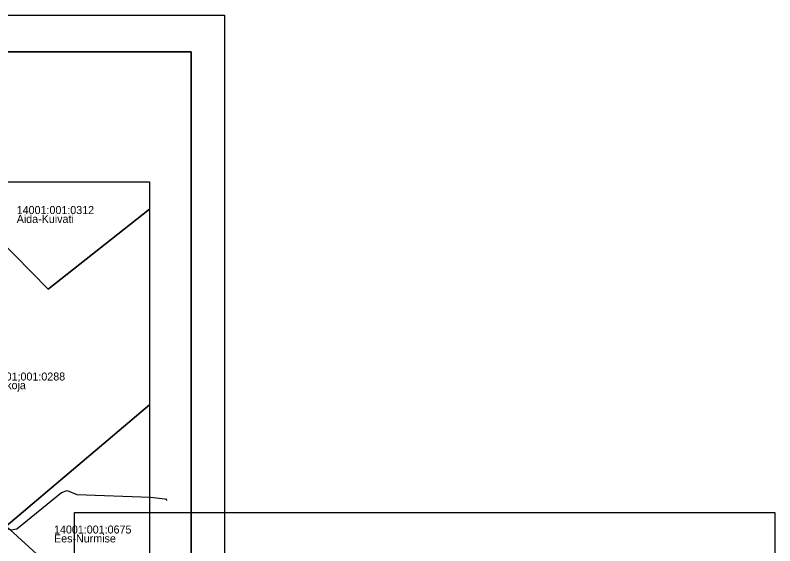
# Model space of a CAD drawing. Extents: x 567864 to 568657, y 6579839 to 6580994.
# Drawn here: x 568478.2 to 568649.1, y 6580409.7 to 6580529 of the extents above; entities that cross this region are included whole.
import ezdxf

# ---------------------------------------------------------------- set-up
doc = ezdxf.new("R2010")
doc.units = 0
for name, color, linetype in [('PIIR', 7, 'Continuous'), ('PR_SIDE', 7, 'Continuous'), ('VORMISTUS_3', 7, 'Continuous'), ('VORMISTUS_4', 7, 'Continuous')]:
    doc.layers.add(name, color=color, linetype=linetype)

msp = doc.modelspace()

# ---------------------------------------------------------------- linework, layer by layer
at = {"layer": 'PIIR'}
for points in [[(568391.3, 6580491.46), (568392.03, 6580490.79), (568429.88, 6580456.3), (568437.22, 6580449.61), (568476.19, 6580414.1), (568508.43, 6580384.73)], [(568508.43, 6580485.34), (568485.66, 6580467.38), (568470.64, 6580482.56), (568461.73, 6580491.46)], [(568508.43, 6580441.35), (568476.19, 6580414.1), (568437.22, 6580449.61), (568470.64, 6580482.56), (568485.66, 6580467.38), (568508.43, 6580485.34)], [(568508.43, 6580384.73), (568476.19, 6580414.1), (568508.43, 6580441.35)]]:
    msp.add_lwpolyline(points, dxfattribs=at)
at = {"layer": 'PR_SIDE'}
msp.add_lwpolyline([(568437.29, 6580453.58), (568437.5, 6580453.08), (568436.5, 6580449.92), (568436.73, 6580448.74), (568445.54, 6580441.11), (568454.95, 6580432.52), (568470.37, 6580418.43), (568474.47, 6580414.72), (568476.09, 6580413.59), (568477.35, 6580413.23), (568478.62, 6580413.47), (568488.63, 6580421.66), (568489.89, 6580422.06), (568492.08, 6580421.21), (568508.66, 6580420.57), (568511.85, 6580420.2), (568512.12, 6580420.13), (568512.34, 6580419.85)], dxfattribs=at)
at = {"layer": 'VORMISTUS_3'}
for points in [[(568367.8, 6580528.96), (568525.3, 6580528.96), (568525.3, 6580306.21), (568367.8, 6580306.21)], [(568375.3, 6580314.46), (568517.8, 6580314.46), (568517.8, 6580520.71), (568375.3, 6580520.71)], [(568375.3, 6580520.71), (568517.8, 6580520.71), (568517.8, 6580314.46), (568375.3, 6580314.46)], [(568508.43, 6580333.96), (568384.68, 6580333.96), (568384.68, 6580491.46), (568508.43, 6580491.46)]]:
    msp.add_lwpolyline(points, close=True, dxfattribs=at)
at = {"layer": 'VORMISTUS_4'}
msp.add_lwpolyline([(568491.55, 6580417.17), (568649.05, 6580417.17), (568649.05, 6580194.42), (568491.55, 6580194.42)], close=True, dxfattribs=at)

# ---------------------------------------------------------------- texts
at = {"layer": 'PIIR'}
for s, p in [('14001:001:0312', (568478.58, 6580484.25)), ('Aida-Kuivati', (568478.58, 6580482.25)), ('14001:001:0288', (568472.07, 6580446.82)), ('Töökoja', (568472.07, 6580444.87)), ('14001:001:0675', (568486.97, 6580412.42)), ('Ees-Nurmise', (568486.97, 6580410.42))]:
    msp.add_text(s, height=1.8, dxfattribs=at).set_placement(p)

doc.saveas('drawing.dxf')
